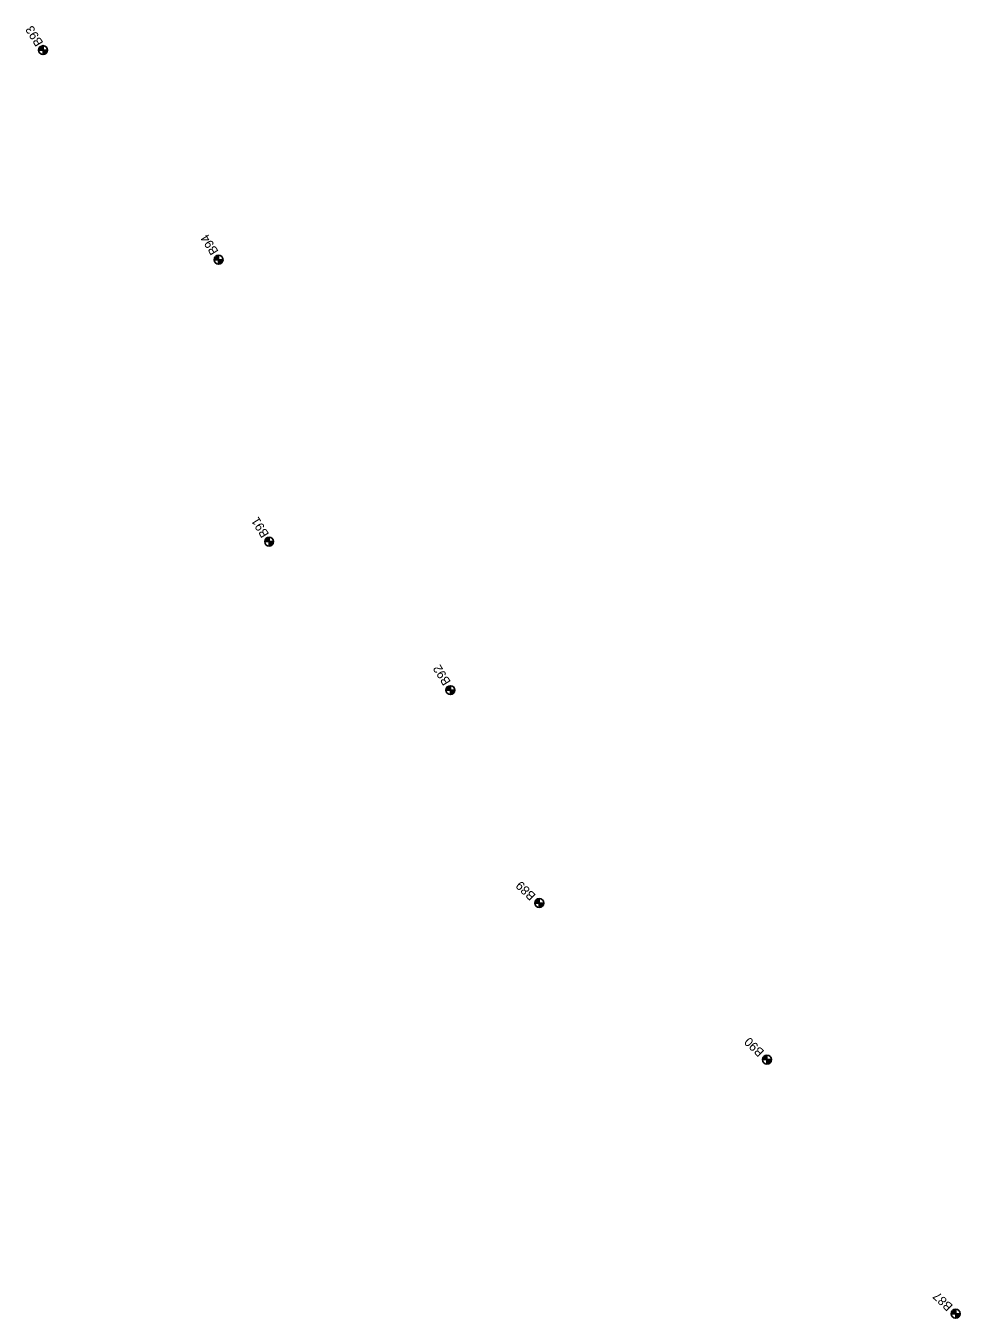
# Model space of a CAD drawing. Extents: x 335726 to 369746, y 119154 to 200788.
# Drawn here: x 356340 to 357387, y 178637 to 180086 of the extents above; entities that cross this region are included whole.
import ezdxf

# ---------------------------------------------------------------- set-up
doc = ezdxf.new("R2010")
doc.units = 0
for name, color, linetype in [('E_SOIL_BORE1 [KAPUR_CADDS_LEVELS]', 7, 'Continuous'), ('E_SOIL_BORE2 [KAPUR_CADDS_LEVELS]', 7, 'Continuous'), ('P_MARK', 7, 'Continuous')]:
    doc.layers.add(name, color=color, linetype=linetype)

msp = doc.modelspace()

# ---------------------------------------------------------------- linework, layer by layer
at = {"layer": 'P_MARK'}
for p, q in [((356354.1, 180059.1), (356364.1, 180059.1)), ((356359.1, 180064.1), (356359.1, 180054.1)), ((356550.7, 179824.1), (356560.7, 179824.1)), ((356555.7, 179829.1), (356555.7, 179819.1)), ((356607.4, 179508), (356617.4, 179508)), ((356612.4, 179513), (356612.4, 179503)), ((356810.5, 179341.5), (356820.5, 179341.5)), ((356815.5, 179346.5), (356815.5, 179336.5)), ((356910, 179102.8), (356920, 179102.8)), ((356915, 179107.8), (356915, 179097.8)), ((357165.2, 178927.2), (357175.2, 178927.2)), ((357170.2, 178932.2), (357170.2, 178922.2)), ((357381.6, 178647.3), (357381.6, 178637.3)), ((357376.6, 178642.3), (357386.6, 178642.3))]:
    msp.add_line(p, q, dxfattribs=at)
for centre in [(356359.1, 180059.1), (356555.7, 179824.1), (356612.4, 179508), (356815.5, 179341.5), (356915, 179102.8), (357170.2, 178927.2), (357381.6, 178642.3)]:
    msp.add_circle(centre, 5, dxfattribs=at)
for centre, radius, start, end in [((356359.1, 180059.1), 4.5, 89.9869, 179.9869), ((356359.1, 180059.1), 4, 89.9869, 179.9869), ((356359.1, 180059.1), 3.5, 89.9869, 179.9869), ((356359.1, 180059.1), 3, 89.9869, 179.9869), ((356359.1, 180059.1), 2.5, 89.9869, 179.9869), ((356359.1, 180059.1), 2, 89.9869, 179.9869), ((356359.1, 180059.1), 1.5, 89.9869, 179.9869), ((356359.1, 180059.1), 1, 89.9869, 179.9869), ((356359.1, 180059.1), 0.5, 89.9869, 179.9869), ((356359.1, 180059.1), 4.5, 269.9869, 359.9869), ((356359.1, 180059.1), 4, 269.9869, 359.9869), ((356359.1, 180059.1), 3.5, 269.9869, 359.9869), ((356359.1, 180059.1), 3, 269.9869, 359.9869), ((356359.1, 180059.1), 2.5, 269.9869, 359.9869), ((356359.1, 180059.1), 2, 269.9869, 359.9869), ((356359.1, 180059.1), 1.5, 269.9869, 359.9869), ((356359.1, 180059.1), 1, 269.9869, 359.9869), ((356359.1, 180059.1), 0.5, 269.9869, 359.9869), ((356555.7, 179824.1), 4.5, 89.9869, 179.9869), ((356555.7, 179824.1), 4, 89.9869, 179.9869), ((356555.7, 179824.1), 3.5, 89.9869, 179.9869), ((356555.7, 179824.1), 3, 89.9869, 179.9869), ((356555.7, 179824.1), 2.5, 89.9869, 179.9869), ((356555.7, 179824.1), 2, 89.9869, 179.9869), ((356555.7, 179824.1), 1.5, 89.9869, 179.9869), ((356555.7, 179824.1), 1, 89.9869, 179.9869), ((356555.7, 179824.1), 0.5, 89.9869, 179.9869), ((356555.7, 179824.1), 4.5, 269.9869, 359.9869), ((356555.7, 179824.1), 4, 269.9869, 359.9869), ((356555.7, 179824.1), 3.5, 269.9869, 359.9869), ((356555.7, 179824.1), 3, 269.9869, 359.9869), ((356555.7, 179824.1), 2.5, 269.9869, 359.9869), ((356555.7, 179824.1), 2, 269.9869, 359.9869), ((356555.7, 179824.1), 1.5, 269.9869, 359.9869), ((356555.7, 179824.1), 1, 269.9869, 359.9869), ((356555.7, 179824.1), 0.5, 269.9869, 359.9869), ((356612.4, 179508), 4.5, 89.9869, 179.9869), ((356612.4, 179508), 4, 89.9869, 179.9869), ((356612.4, 179508), 3.5, 89.9869, 179.9869), ((356612.4, 179508), 3, 89.9869, 179.9869), ((356612.4, 179508), 2.5, 89.9869, 179.9869), ((356612.4, 179508), 2, 89.9869, 179.9869), ((356612.4, 179508), 1.5, 89.9869, 179.9869), ((356612.4, 179508), 1, 89.9869, 179.9869), ((356612.4, 179508), 0.5, 89.9869, 179.9869), ((356612.4, 179508), 4.5, 269.9869, 359.9869), ((356612.4, 179508), 4, 269.9869, 359.9869), ((356612.4, 179508), 3.5, 269.9869, 359.9869), ((356612.4, 179508), 3, 269.9869, 359.9869), ((356612.4, 179508), 2.5, 269.9869, 359.9869), ((356612.4, 179508), 2, 269.9869, 359.9869), ((356612.4, 179508), 1.5, 269.9869, 359.9869), ((356612.4, 179508), 1, 269.9869, 359.9869), ((356612.4, 179508), 0.5, 269.9869, 359.9869), ((356815.5, 179341.5), 4.5, 89.9869, 179.9869), ((356815.5, 179341.5), 4, 89.9869, 179.9869), ((356815.5, 179341.5), 3.5, 89.9869, 179.9869), ((356815.5, 179341.5), 3, 89.9869, 179.9869), ((356815.5, 179341.5), 2.5, 89.9869, 179.9869), ((356815.5, 179341.5), 2, 89.9869, 179.9869), ((356815.5, 179341.5), 1.5, 89.9869, 179.9869), ((356815.5, 179341.5), 1, 89.9869, 179.9869), ((356815.5, 179341.5), 0.5, 89.9869, 179.9869), ((356815.5, 179341.5), 4.5, 269.9869, 359.9869), ((356815.5, 179341.5), 4, 269.9869, 359.9869), ((356815.5, 179341.5), 3.5, 269.9869, 359.9869), ((356815.5, 179341.5), 3, 269.9869, 359.9869), ((356815.5, 179341.5), 2.5, 269.9869, 359.9869), ((356815.5, 179341.5), 2, 269.9869, 359.9869), ((356815.5, 179341.5), 1.5, 269.9869, 359.9869), ((356815.5, 179341.5), 1, 269.9869, 359.9869), ((356815.5, 179341.5), 0.5, 269.9869, 359.9869), ((356915, 179102.8), 4.5, 89.9869, 179.9869), ((356915, 179102.8), 4, 89.9869, 179.9869), ((356915, 179102.8), 3.5, 89.9869, 179.9869), ((356915, 179102.8), 3, 89.9869, 179.9869), ((356915, 179102.8), 2.5, 89.9869, 179.9869), ((356915, 179102.8), 2, 89.9869, 179.9869), ((356915, 179102.8), 1.5, 89.9869, 179.9869), ((356915, 179102.8), 1, 89.9869, 179.9869), ((356915, 179102.8), 0.5, 89.9869, 179.9869), ((356915, 179102.8), 4.5, 269.9869, 359.9869), ((356915, 179102.8), 4, 269.9869, 359.9869), ((356915, 179102.8), 3.5, 269.9869, 359.9869), ((356915, 179102.8), 3, 269.9869, 359.9869), ((356915, 179102.8), 2.5, 269.9869, 359.9869), ((356915, 179102.8), 2, 269.9869, 359.9869), ((356915, 179102.8), 1.5, 269.9869, 359.9869), ((356915, 179102.8), 1, 269.9869, 359.9869), ((356915, 179102.8), 0.5, 269.9869, 359.9869), ((357170.2, 178927.2), 4.5, 89.9869, 179.9869), ((357170.2, 178927.2), 4, 89.9869, 179.9869), ((357170.2, 178927.2), 3.5, 89.9869, 179.9869), ((357170.2, 178927.2), 3, 89.9869, 179.9869), ((357170.2, 178927.2), 2.5, 89.9869, 179.9869), ((357170.2, 178927.2), 2, 89.9869, 179.9869), ((357170.2, 178927.2), 1.5, 89.9869, 179.9869), ((357170.2, 178927.2), 1, 89.9869, 179.9869), ((357170.2, 178927.2), 0.5, 89.9869, 179.9869), ((357170.2, 178927.2), 4.5, 269.9869, 359.9869), ((357170.2, 178927.2), 4, 269.9869, 359.9869), ((357170.2, 178927.2), 3.5, 269.9869, 359.9869), ((357170.2, 178927.2), 3, 269.9869, 359.9869), ((357170.2, 178927.2), 2.5, 269.9869, 359.9869), ((357170.2, 178927.2), 2, 269.9869, 359.9869), ((357170.2, 178927.2), 1.5, 269.9869, 359.9869), ((357170.2, 178927.2), 1, 269.9869, 359.9869), ((357170.2, 178927.2), 0.5, 269.9869, 359.9869), ((357381.6, 178642.3), 4.5, 89.9869, 179.9869), ((357381.6, 178642.3), 4, 89.9869, 179.9869), ((357381.6, 178642.3), 3.5, 89.9869, 179.9869), ((357381.6, 178642.3), 3, 89.9869, 179.9869), ((357381.6, 178642.3), 2.5, 89.9869, 179.9869), ((357381.6, 178642.3), 2, 89.9869, 179.9869), ((357381.6, 178642.3), 1.5, 89.9869, 179.9869), ((357381.6, 178642.3), 1, 89.9869, 179.9869), ((357381.6, 178642.3), 0.5, 89.9869, 179.9869), ((357381.6, 178642.3), 4.5, 269.9869, 359.9869), ((357381.6, 178642.3), 4, 269.9869, 359.9869), ((357381.6, 178642.3), 3.5, 269.9869, 359.9869), ((357381.6, 178642.3), 3, 269.9869, 359.9869), ((357381.6, 178642.3), 2.5, 269.9869, 359.9869), ((357381.6, 178642.3), 2, 269.9869, 359.9869), ((357381.6, 178642.3), 1.5, 269.9869, 359.9869), ((357381.6, 178642.3), 1, 269.9869, 359.9869), ((357381.6, 178642.3), 0.5, 269.9869, 359.9869)]:
    msp.add_arc(centre, radius, start, end, dxfattribs=at)

# ---------------------------------------------------------------- texts
at = {"layer": 'E_SOIL_BORE1 [KAPUR_CADDS_LEVELS]'}
for s, p in [('B89', (356911.8, 179111.8)), ('B90', (357167.8, 178936.6)), ('B87', (357379.1, 178651.4))]:
    msp.add_text(s, height=10, rotation=136.1942, dxfattribs=at).set_placement(p)
at = {"layer": 'E_SOIL_BORE2 [KAPUR_CADDS_LEVELS]'}
for s, p in [('B93', (356359.7, 180067.3)), ('B94', (356556, 179833.4)), ('B91', (356612.7, 179516.4)), ('B92', (356816.3, 179350.8))]:
    msp.add_text(s, height=10, rotation=121.7799, dxfattribs=at).set_placement(p)

doc.saveas('drawing.dxf')
